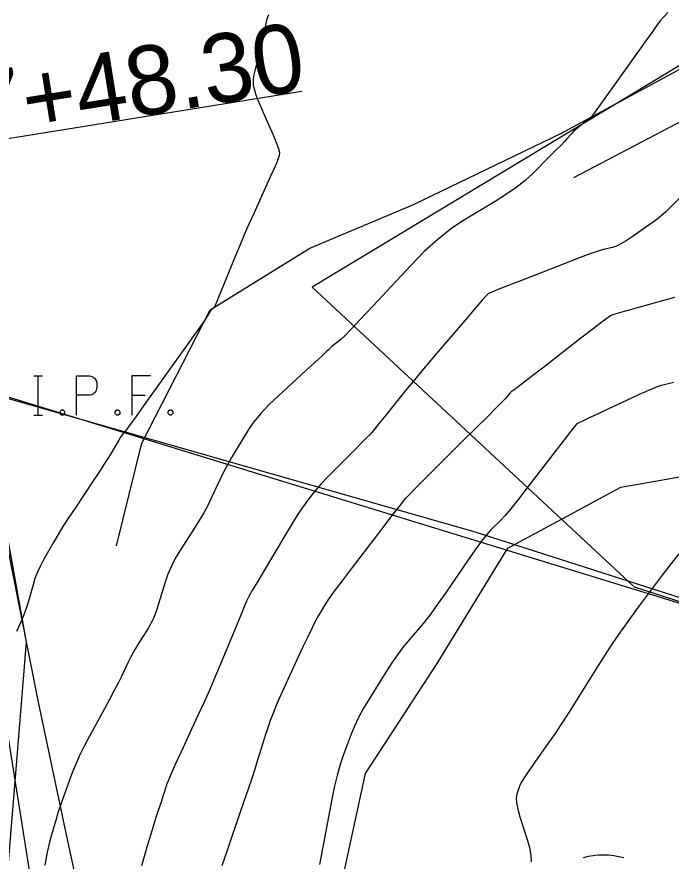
# Model space of a CAD drawing. Extents: x 2030588 to 2035216, y 462285 to 465007.
# Drawn here: x 2031297.29 to 2031323.89, y 464206.38 to 464240.7 of the extents above; entities that cross this region are included whole.
import ezdxf

# ---------------------------------------------------------------- set-up
doc = ezdxf.new("R2010")
doc.units = 0
for name, color, linetype in [('DT_X_Contour_Major', 7, 'Continuous'), ('DT_X_Contour_Minor', 7, 'Continuous'), ('DV_X_Property_Line', 7, 'Continuous'), ('HY_X_Water_Well', 7, 'Continuous'), ('MD_P_CONST_LIMITS', 7, 'Continuous'), ('RD_X_Fence', 7, 'Continuous'), ('RW_X_CL', 7, 'Continuous'), ('RW_X_CL_100_Cardinal_Points', 7, 'Continuous'), ('RW_X_Esmt_SH', 7, 'Continuous'), ('SV_X_Break_Lines', 7, 'Continuous'), ('SV_X_Mon_Cells_Found', 7, 'Continuous'), ('SV_X_Toe_of_Slope', 7, 'Continuous'), ('SV_X_Top_of_Bank', 7, 'Continuous'), ('UT_X_Electric', 7, 'Continuous'), ('VG_X_Tree_Line_Rt', 7, 'Continuous')]:
    doc.layers.add(name, color=color, linetype=linetype)

msp = doc.modelspace()

# ---------------------------------------------------------------- linework, layer by layer
at = {"layer": 'DT_X_Contour_Major'}
for points in [[(2031307.512, 464240.784), (2031307.433, 464240.569), (2031307.333, 464240.042), (2031307.293, 464239.841), (2031307.247, 464239.63), (2031307.195, 464239.411), (2031307.137, 464239.183), (2031306.976, 464238.564), (2031306.926, 464238.35), (2031306.896, 464238.172), (2031306.887, 464238.029), (2031306.898, 464237.923), (2031306.954, 464237.686), (2031306.992, 464237.566), (2031307.062, 464237.381), (2031307.165, 464237.132), (2031307.3, 464236.819), (2031307.703, 464235.9), (2031307.832, 464235.589), (2031307.917, 464235.346), (2031307.957, 464235.171), (2031307.953, 464235.064), (2031307.883, 464234.868), (2031307.836, 464234.75), (2031307.746, 464234.542), (2031307.613, 464234.245), (2031307.439, 464233.859), (2031306.916, 464232.71), (2031306.722, 464232.278), (2031306.531, 464231.843), (2031306.344, 464231.405), (2031306.161, 464230.964), (2031305.316, 464228.898), (2031305.229, 464228.814), (2031305.213, 464228.798), (2031305.2, 464228.785), (2031305.19, 464228.776), (2031305.184, 464228.77), (2031305.174, 464228.76), (2031305.166, 464228.75), (2031305.15, 464228.726), (2031305.126, 464228.689), (2031305.095, 464228.638), (2031304.929, 464228.369), (2031302.779, 464225.36), (2031302.37, 464224.788), (2031302.062, 464224.361), (2031301.857, 464224.081), (2031301.755, 464223.946), (2031301.617, 464223.781), (2031301.561, 464223.708), (2031301.497, 464223.614), (2031301.425, 464223.499), (2031301.344, 464223.362), (2031301.117, 464222.969), (2031301.008, 464222.788), (2031300.851, 464222.54), (2031300.646, 464222.225), (2031300.392, 464221.843), (2031299.652, 464220.735), (2031299.39, 464220.338), (2031299.159, 464219.978), (2031298.96, 464219.654), (2031298.791, 464219.367), (2031298.384, 464218.652), (2031298.242, 464218.386), (2031298.12, 464218.125), (2031298.02, 464217.869), (2031297.941, 464217.618), (2031297.758, 464216.955), (2031297.676, 464216.691), (2031297.566, 464216.396), (2031297.429, 464216.069), (2031297.265, 464215.712)], [(2031324.196, 464218.875), (2031323.883, 464218.484), (2031323.523, 464218.012), (2031322.501, 464216.647), (2031322.121, 464216.128), (2031321.747, 464215.595), (2031321.38, 464215.046), (2031321.02, 464214.484), (2031320.069, 464212.963), (2031319.728, 464212.424), (2031319.418, 464211.947), (2031319.14, 464211.531), (2031318.894, 464211.177), (2031318.279, 464210.315), (2031318.072, 464210.017), (2031317.911, 464209.77), (2031317.796, 464209.573), (2031317.728, 464209.427), (2031317.61, 464209.105), (2031317.584, 464208.956), (2031317.598, 464208.752), (2031317.65, 464208.492), (2031317.74, 464208.177), (2031318.034, 464207.261), (2031318.125, 464206.932), (2031318.178, 464206.63), (2031318.194, 464206.358)]]:
    msp.add_lwpolyline(points, dxfattribs=at)
at = {"layer": 'DT_X_Contour_Minor'}
for points in [[(2031323.758, 464240.875), (2031323.586, 464240.698), (2031323.441, 464240.533), (2031323.324, 464240.38), (2031323.046, 464239.988), (2031322.914, 464239.802), (2031322.726, 464239.538), (2031322.482, 464239.196), (2031322.183, 464238.775), (2031320.655, 464236.631), (2031320.177, 464236.256), (2031320.079, 464236.177), (2031319.989, 464236.098), (2031319.908, 464236.02), (2031319.834, 464235.943), (2031319.651, 464235.738), (2031319.557, 464235.638), (2031319.413, 464235.489), (2031319.219, 464235.292), (2031318.975, 464235.048), (2031318.259, 464234.332), (2031317.962, 464234.059), (2031317.609, 464233.78), (2031317.2, 464233.493), (2031316.736, 464233.2), (2031315.421, 464232.407), (2031314.919, 464232.07), (2031314.395, 464231.653), (2031313.852, 464231.157), (2031313.289, 464230.582), (2031311.759, 464228.943), (2031311.248, 464228.398), (2031310.863, 464227.992), (2031310.602, 464227.726), (2031310.468, 464227.6), (2031310.275, 464227.45), (2031310.207, 464227.396), (2031310.148, 464227.347), (2031310.097, 464227.302), (2031310.054, 464227.262), (2031309.951, 464227.161), (2031309.865, 464227.08), (2031309.684, 464226.913), (2031309.408, 464226.66), (2031309.037, 464226.321), (2031307.923, 464225.302), (2031307.533, 464224.93), (2031307.201, 464224.575), (2031306.925, 464224.239), (2031306.707, 464223.921), (2031306.2, 464223.098), (2031306.017, 464222.792), (2031305.848, 464222.491), (2031305.692, 464222.194), (2031305.55, 464221.903), (2031305.189, 464221.132), (2031305.045, 464220.838), (2031304.881, 464220.535), (2031304.699, 464220.222), (2031304.498, 464219.901), (2031303.938, 464219.031), (2031303.741, 464218.704), (2031303.572, 464218.377), (2031303.43, 464218.049), (2031303.316, 464217.72), (2031303.047, 464216.842), (2031302.944, 464216.53), (2031302.834, 464216.252), (2031302.719, 464216.01), (2031302.599, 464215.802), (2031302.269, 464215.293), (2031302.147, 464215.098), (2031302.03, 464214.895), (2031301.917, 464214.683), (2031301.808, 464214.463), (2031301.522, 464213.865), (2031301.4, 464213.617), (2031301.247, 464213.319), (2031301.063, 464212.973), (2031300.849, 464212.579), (2031300.236, 464211.461), (2031300.021, 464211.056), (2031299.835, 464210.679), (2031299.678, 464210.329), (2031299.551, 464210.008), (2031299.25, 464209.187), (2031299.142, 464208.888), (2031299.044, 464208.606), (2031298.957, 464208.342), (2031298.88, 464208.094), (2031298.688, 464207.455), (2031298.61, 464207.158), (2031298.521, 464206.745), (2031298.42, 464206.216)], [(2031324.291, 464233.404), (2031323.85, 464232.95), (2031323.673, 464232.778), (2031323.472, 464232.603), (2031323.248, 464232.426), (2031323, 464232.245), (2031322.308, 464231.759), (2031322.063, 464231.595), (2031321.847, 464231.469), (2031321.661, 464231.38), (2031321.504, 464231.328), (2031321.125, 464231.24), (2031320.919, 464231.179), (2031320.586, 464231.063), (2031320.126, 464230.892), (2031319.538, 464230.666), (2031317.801, 464229.99), (2031317.229, 464229.766), (2031316.817, 464229.604), (2031316.564, 464229.502), (2031316.47, 464229.461), (2031316.433, 464229.433), (2031316.37, 464229.364), (2031316.209, 464229.18), (2031315.949, 464228.88), (2031315.592, 464228.464), (2031314.51, 464227.202), (2031314.117, 464226.741), (2031313.749, 464226.305), (2031313.407, 464225.893), (2031313.091, 464225.507), (2031312.283, 464224.509), (2031312.017, 464224.181), (2031311.828, 464223.947), (2031311.713, 464223.806), (2031311.675, 464223.759), (2031311.673, 464223.756), (2031311.632, 464223.716), (2031311.513, 464223.596), (2031311.315, 464223.397), (2031311.039, 464223.118), (2031310.196, 464222.27), (2031309.904, 464221.972), (2031309.662, 464221.715), (2031309.468, 464221.498), (2031309.324, 464221.322), (2031309.005, 464220.907), (2031308.862, 464220.706), (2031308.672, 464220.416), (2031308.436, 464220.035), (2031308.152, 464219.566), (2031307.335, 464218.193), (2031307.065, 464217.739), (2031306.869, 464217.407), (2031306.746, 464217.197), (2031306.697, 464217.109), (2031306.663, 464217.037), (2031306.624, 464216.946), (2031306.532, 464216.725), (2031306.387, 464216.376), (2031306.189, 464215.899), (2031305.59, 464214.453), (2031305.361, 464213.909), (2031305.125, 464213.364), (2031304.882, 464212.817), (2031304.631, 464212.268), (2031303.951, 464210.8), (2031303.725, 464210.308), (2031303.556, 464209.932), (2031303.444, 464209.672), (2031303.389, 464209.529), (2031303.319, 464209.301), (2031303.289, 464209.207), (2031303.253, 464209.096), (2031303.21, 464208.966), (2031303.16, 464208.82), (2031303.017, 464208.405), (2031302.936, 464208.15), (2031302.797, 464207.695), (2031302.602, 464207.041), (2031302.351, 464206.187)], [(2031324.029, 464229.288), (2031323.631, 464229.18), (2031322.463, 464228.862), (2031322.075, 464228.756), (2031321.788, 464228.675), (2031321.602, 464228.62), (2031321.516, 464228.591), (2031321.423, 464228.547), (2031321.321, 464228.478), (2031321.086, 464228.302), (2031320.719, 464228.021), (2031320.218, 464227.635), (2031318.706, 464226.462), (2031318.206, 464226.075), (2031317.84, 464225.793), (2031317.608, 464225.615), (2031317.51, 464225.543), (2031317.427, 464225.489), (2031317.397, 464225.467), (2031317.366, 464225.439), (2031317.335, 464225.407), (2031317.305, 464225.37), (2031317.223, 464225.264), (2031317.15, 464225.183), (2031316.991, 464225.02), (2031316.746, 464224.775), (2031316.415, 464224.448), (2031315.419, 464223.465), (2031315.064, 464223.113), (2031314.743, 464222.795), (2031314.458, 464222.511), (2031314.209, 464222.26), (2031313.59, 464221.636), (2031313.386, 464221.43), (2031313.235, 464221.278), (2031313.14, 464221.182), (2031313.098, 464221.14), (2031313.06, 464221.102), (2031312.991, 464221.015), (2031312.812, 464220.785), (2031312.524, 464220.411), (2031312.125, 464219.892), (2031310.916, 464218.318), (2031310.507, 464217.781), (2031310.187, 464217.349), (2031309.955, 464217.024), (2031309.812, 464216.805), (2031309.548, 464216.361), (2031309.433, 464216.155), (2031309.287, 464215.87), (2031309.11, 464215.504), (2031308.901, 464215.059), (2031308.303, 464213.765), (2031308.099, 464213.322), (2031307.938, 464212.962), (2031307.818, 464212.686), (2031307.741, 464212.494), (2031307.59, 464212.093), (2031307.529, 464211.925), (2031307.46, 464211.722), (2031307.383, 464211.485), (2031307.298, 464211.213), (2031307.06, 464210.442), (2031306.96, 464210.123), (2031306.835, 464209.743), (2031306.688, 464209.302), (2031306.517, 464208.8), (2031306.029, 464207.381), (2031305.862, 464206.894), (2031305.726, 464206.496), (2031305.621, 464206.188)], [(2031323.988, 464225.842), (2031323.661, 464225.761), (2031323.437, 464225.7), (2031323.315, 464225.661), (2031323.127, 464225.585), (2031323.02, 464225.539), (2031322.843, 464225.459), (2031322.593, 464225.345), (2031322.272, 464225.196), (2031321.32, 464224.755), (2031320.998, 464224.605), (2031320.745, 464224.487), (2031320.561, 464224.4), (2031320.447, 464224.346), (2031320.234, 464224.242), (2031320.163, 464224.207), (2031320.109, 464224.181), (2031320.073, 464224.162), (2031320.054, 464224.152), (2031320.028, 464224.135), (2031319.967, 464224.061), (2031319.805, 464223.854), (2031319.541, 464223.513), (2031319.175, 464223.037), (2031318.064, 464221.591), (2031317.681, 464221.099), (2031317.367, 464220.707), (2031317.122, 464220.415), (2031316.944, 464220.224), (2031316.563, 464219.848), (2031316.396, 464219.663), (2031316.181, 464219.391), (2031315.917, 464219.032), (2031315.605, 464218.585), (2031314.708, 464217.278), (2031314.391, 464216.822), (2031314.11, 464216.435), (2031313.868, 464216.117), (2031313.662, 464215.868), (2031313.164, 464215.295), (2031312.969, 464215.057), (2031312.758, 464214.772), (2031312.531, 464214.44), (2031312.288, 464214.061), (2031311.618, 464212.988), (2031311.383, 464212.596), (2031311.181, 464212.224), (2031311.01, 464211.872), (2031310.873, 464211.54), (2031310.548, 464210.682), (2031310.426, 464210.315), (2031310.302, 464209.861), (2031310.177, 464209.317), (2031310.051, 464208.685), (2031309.714, 464206.88), (2031309.588, 464206.248)]]:
    msp.add_lwpolyline(points, dxfattribs=at)
at = {"layer": 'DV_X_Property_Line'}
msp.add_line((2031636.207, 464120.963), (2031264.413, 464235.242), dxfattribs=at)
at = {"layer": 'HY_X_Water_Well'}
msp.add_ellipse((2031321.132, 464203.629), major_axis=(-2.01, 2.227), ratio=0.999987, start_param=5.268586, end_param=5.827016, dxfattribs=at)
at = {"layer": 'MD_P_CONST_LIMITS'}
msp.add_lwpolyline([(2031304.871, 464099.462), (2031318.532, 464105.655), (2031311.904, 464118.546), (2031304.38, 464141.463), (2031297.225, 464164.67), (2031295.574, 464189.665), (2031297.675, 464215.284), (2031293.386, 464239.179), (2031288.691, 464262.969), (2031290.634, 464288.11), (2031294.17, 464303.872), (2031299.488, 464314.858)], dxfattribs=at)
at = {"layer": 'RD_X_Fence'}
msp.add_lwpolyline([(2031296.661, 464225.271), (2031315.862, 464219.785), (2031324.624, 464216.973), (2031330.829, 464230.155), (2031335.011, 464242.221), (2031347.019, 464246.547), (2031359.451, 464251.293)], dxfattribs=at)
at = {"layer": 'RW_X_CL'}
msp.add_ellipse((2031830.081, 464321.523), major_axis=(-382.715, 426.319), ratio=0.999987, start_param=0.998751, end_param=1.776295, dxfattribs=at)
at = {"layer": 'RW_X_CL_100_Cardinal_Points'}
msp.add_line((2031264.454, 464230.531), (2031308.878, 464237.678), dxfattribs=at)
at = {"layer": 'RW_X_Esmt_SH'}
msp.add_lwpolyline([(2031309.17, 464168.574), (2031307.591, 464174.056), (2031306.071, 464179.554), (2031304.608, 464185.068), (2031303.203, 464190.596), (2031301.856, 464196.14), (2031300.568, 464201.697), (2031299.338, 464207.267), (2031298.167, 464212.85), (2031297.054, 464218.445), (2031296.001, 464224.051), (2031295.006, 464229.668), (2031294.07, 464235.295)], dxfattribs=at)
at = {"layer": 'SV_X_Break_Lines'}
msp.add_lwpolyline([(2031319.927, 464234.169), (2031326.851, 464237.795), (2031331.994, 464240.964), (2031338.603, 464243.362), (2031344.003, 464245.049), (2031350.731, 464247.579), (2031355.08, 464249.168), (2031358.112, 464250.597), (2031360.099, 464251.636)], dxfattribs=at)
at = {"layer": 'SV_X_Mon_Cells_Found'}
for p, q in [((2031297.971, 464226.108), (2031298.323, 464226.108)), ((2031298.147, 464224.508), (2031298.147, 464226.108)), ((2031301.961, 464225.327), (2031302.501, 464225.327)), ((2031297.971, 464224.508), (2031298.323, 464224.508))]:
    msp.add_line(p, q, dxfattribs=at)
for points in [[(2031299.712, 464224.508), (2031299.712, 464226.108), (2031300.241, 464226.108), (2031300.296, 464226.095), (2031300.374, 464226.07), (2031300.407, 464226.045), (2031300.44, 464226.019), (2031300.484, 464225.956), (2031300.517, 464225.893), (2031300.539, 464225.793), (2031300.539, 464225.641), (2031300.528, 464225.591), (2031300.506, 464225.516), (2031300.462, 464225.427), (2031300.418, 464225.39), (2031300.385, 464225.364), (2031300.329, 464225.339), (2031300.241, 464225.327), (2031299.712, 464225.327)], [(2031302.721, 464226.108), (2031301.961, 464226.108), (2031301.961, 464224.508)], [(2031299.106, 464224.722), (2031299.161, 464224.722), (2031299.194, 464224.697), (2031299.227, 464224.646), (2031299.227, 464224.583), (2031299.194, 464224.533), (2031299.161, 464224.508), (2031299.106, 464224.508), (2031299.073, 464224.533), (2031299.04, 464224.583), (2031299.04, 464224.646), (2031299.073, 464224.697), (2031299.106, 464224.722)], [(2031301.355, 464224.722), (2031301.41, 464224.722), (2031301.443, 464224.697), (2031301.476, 464224.646), (2031301.476, 464224.583), (2031301.443, 464224.533), (2031301.41, 464224.508), (2031301.355, 464224.508), (2031301.321, 464224.533), (2031301.288, 464224.583), (2031301.288, 464224.646), (2031301.321, 464224.697), (2031301.355, 464224.722)], [(2031303.504, 464224.722), (2031303.559, 464224.722), (2031303.592, 464224.697), (2031303.625, 464224.646), (2031303.625, 464224.583), (2031303.592, 464224.533), (2031303.559, 464224.508), (2031303.504, 464224.508), (2031303.471, 464224.533), (2031303.438, 464224.583), (2031303.438, 464224.646), (2031303.471, 464224.697), (2031303.504, 464224.722)]]:
    msp.add_lwpolyline(points, dxfattribs=at)
at = {"layer": 'SV_X_Toe_of_Slope'}
msp.add_lwpolyline([(2031301.333, 464219.202), (2031302.369, 464223.373), (2031305.147, 464228.794), (2031309.193, 464231.294), (2031313.387, 464233.058), (2031319.404, 464235.956), (2031326.131, 464239.587), (2031331.9, 464241.924), (2031337.739, 464244.421), (2031343.314, 464246.669), (2031346.012, 464249.11), (2031349.429, 464251.511), (2031351.93, 464253.731), (2031356.219, 464255.225), (2031362.014, 464257.768)], dxfattribs=at)
at = {"layer": 'SV_X_Top_of_Bank'}
msp.add_lwpolyline([(2031308.359, 464198.637), (2031309.978, 464203.134), (2031311.463, 464209.947), (2031314.369, 464214.416), (2031317.251, 464219.098), (2031321.845, 464221.581), (2031328.27, 464222.703), (2031336.257, 464224.396), (2031345.747, 464226.457), (2031351.201, 464228.048), (2031357.928, 464229.615), (2031366.658, 464231.2)], dxfattribs=at)
at = {"layer": 'UT_X_Electric'}
msp.add_lwpolyline([(2031221.843, 464713.466), (2031231.941, 464645.283), (2031244.284, 464562.24), (2031252.852, 464504.34), (2031260, 464456.218), (2031264.868, 464423.288), (2031269.313, 464393.306), (2031274.036, 464361.48), (2031280.969, 464314.78), (2031288.221, 464265.917), (2031292.226, 464240.822), (2031300.292, 464190.304), (2031337.855, 463955.944)], dxfattribs=at)
at = {"layer": 'VG_X_Tree_Line_Rt'}
msp.add_lwpolyline([(2031364.273, 464254.235), (2031331.692, 464243.234), (2031309.291, 464229.711), (2031322.387, 464217.533), (2031366.537, 464203.31)], dxfattribs=at)

# ---------------------------------------------------------------- texts
at = {"layer": 'RW_X_CL_100_Cardinal_Points'}
msp.add_text('147+48.30', height=2.7997, rotation=9.1388, dxfattribs=at).set_placement((2031291.559, 464234.929))

doc.saveas('drawing.dxf')
